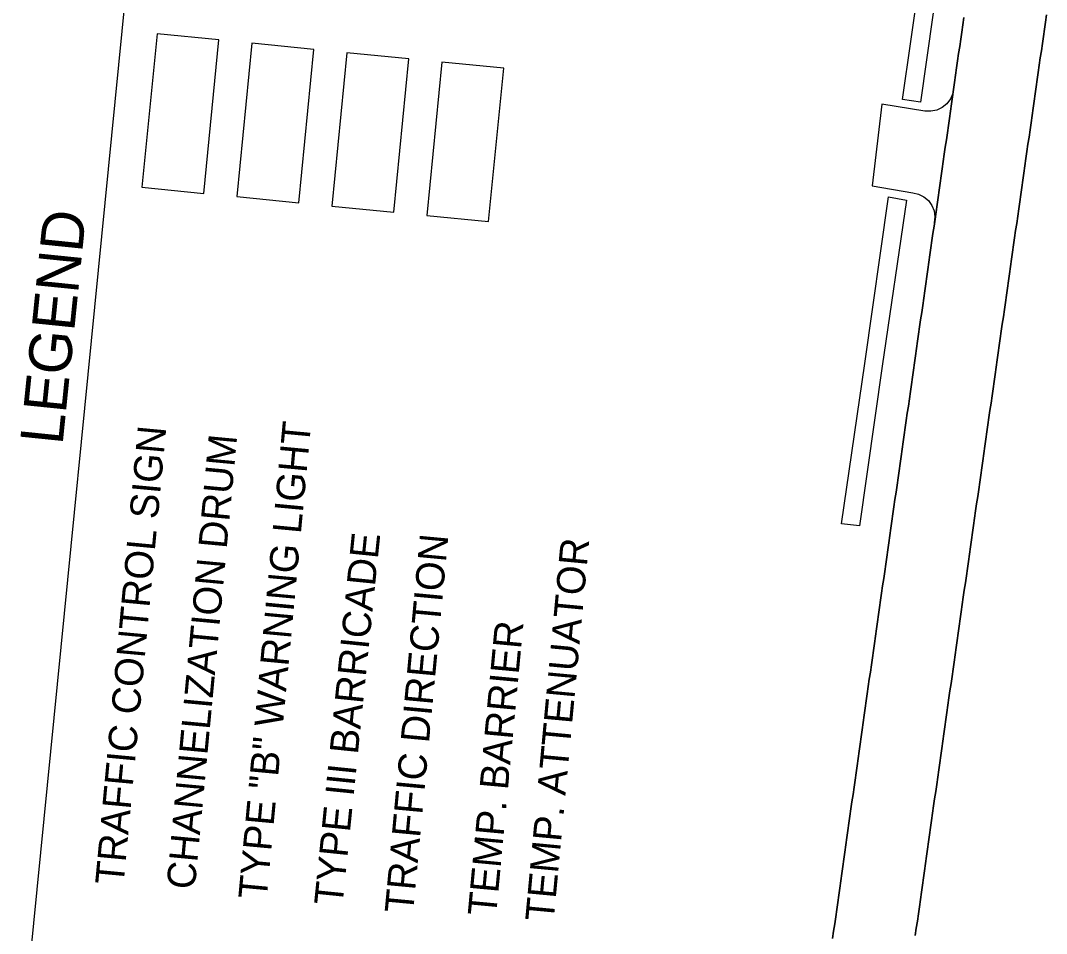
# Model space of a CAD drawing. Extents: x 1795987 to 1799700, y 243690 to 251545.
# Drawn here: x 1797261.2 to 1797542.5, y 247202.7 to 247453.1 of the extents above; entities that cross this region are included whole.
import ezdxf

# ---------------------------------------------------------------- set-up
doc = ezdxf.new("R2010")
doc.units = 0
for name, color, linetype in [('EP', 7, 'Continuous'), ('Level 31', 7, 'Continuous'), ('Prop_Horiz Alignment', 7, 'Continuous')]:
    doc.layers.add(name, color=color, linetype=linetype)

msp = doc.modelspace()

# ---------------------------------------------------------------- linework, layer by layer
at = {"layer": 'EP'}
for p, q in [((1797507.92, 247430.67), (1797502.98, 247431.42)), ((1797499.19, 247404.72), (1797504.07, 247403.85)), ((1797491.2, 247314.5), (1797486.32, 247315.04))]:
    msp.add_line(p, q, dxfattribs=at)
for points in [[(1797502.98, 247431.42), (1797509.89, 247479.28), (1797512.41, 247496.92), (1797513.21, 247499.92), (1797514.39, 247502.79), (1797515.55, 247504.9), (1797517.77, 247509.13), (1797519.86, 247513.31), (1797520.78, 247515.42), (1797521.93, 247518.67), (1797522.28, 247519.96), (1797522.83, 247522.6), (1797523.1, 247524.61), (1797523.26, 247527.63), (1797523.1, 247531.02), (1797522.82, 247533.27), (1797521.91, 247537.81), (1797521.35, 247540.15), (1797520.54, 247543.7), (1797520.12, 247547.31), (1797520.09, 247550.71), (1797523.74, 247576.05), (1797530.2, 247621.54), (1797536.99, 247668.47)], [(1797541.84, 247667.67), (1797535.11, 247620.83), (1797528.62, 247575.39), (1797524.96, 247549.93), (1797525.06, 247548.02), (1797525.55, 247543.91), (1797526.45, 247539.86), (1797526.65, 247538.96), (1797527.41, 247535.59), (1797527.98, 247531.38), (1797528.16, 247527.13), (1797526.97, 247518.48), (1797526.28, 247516.25), (1797524.64, 247511.95), (1797522.63, 247507.8), (1797522.17, 247506.93), (1797521.53, 247505.59), (1797517.43, 247496.48), (1797514.72, 247478.52), (1797507.92, 247430.67)], [(1797486.32, 247315.04), (1797492.66, 247359.05), (1797499.19, 247404.72)], [(1797504.07, 247403.85), (1797497.45, 247358.32), (1797491.2, 247314.5)]]:
    msp.add_lwpolyline(points, dxfattribs=at)
at = {"layer": 'Level 31'}
msp.add_line((1797261.35, 247170.53), (1797308.29, 247644.28), dxfattribs=at)
for points in [[(1797311.42, 247405.67), (1797315.58, 247447.74), (1797298.6, 247449.42), (1797294.43, 247407.35)], [(1797337.45, 247403.09), (1797341.62, 247445.16), (1797324.63, 247446.84), (1797320.46, 247404.77)], [(1797363.49, 247400.51), (1797367.66, 247442.58), (1797350.67, 247444.26), (1797346.5, 247402.19)], [(1797389.53, 247397.93), (1797393.69, 247440), (1797376.71, 247441.68), (1797372.54, 247399.61)]]:
    msp.add_lwpolyline(points, close=True, dxfattribs=at)
at = {"layer": 'Prop_Horiz Alignment'}
for points in [[(1797542.49, 247454.65), (1797542.21, 247452.67), (1797541.93, 247450.7), (1797541.65, 247448.73), (1797541.36, 247446.76), (1797541.08, 247444.78), (1797540.8, 247442.81), (1797540.52, 247440.84), (1797540.24, 247438.87), (1797539.96, 247436.89), (1797539.67, 247434.92), (1797539.39, 247432.95), (1797539.11, 247430.98), (1797538.83, 247429), (1797538.55, 247427.03), (1797538.27, 247425.06), (1797537.99, 247423.09), (1797537.7, 247421.11), (1797537.42, 247419.14), (1797537.14, 247417.17), (1797536.86, 247415.2), (1797536.58, 247413.22), (1797536.3, 247411.25), (1797536.01, 247409.28), (1797535.73, 247407.31), (1797535.45, 247405.33), (1797535.17, 247403.36), (1797534.89, 247401.39), (1797534.61, 247399.42), (1797534.32, 247397.44), (1797534.04, 247395.47), (1797533.76, 247393.5), (1797533.48, 247391.53), (1797533.2, 247389.56), (1797532.92, 247387.58), (1797532.64, 247385.61), (1797532.35, 247383.64), (1797532.07, 247381.67), (1797531.79, 247379.69), (1797531.51, 247377.72), (1797531.23, 247375.75), (1797530.95, 247373.78), (1797530.66, 247371.8), (1797530.38, 247369.83), (1797530.1, 247367.86), (1797529.82, 247365.89), (1797529.54, 247363.91), (1797529.26, 247361.94), (1797528.98, 247359.97), (1797528.69, 247358), (1797528.41, 247356.02), (1797528.13, 247354.05), (1797527.85, 247352.08), (1797527.57, 247350.11), (1797527.29, 247348.13), (1797527, 247346.16), (1797526.72, 247344.19), (1797526.44, 247342.22), (1797526.16, 247340.24), (1797525.88, 247338.27), (1797525.6, 247336.3), (1797525.31, 247334.33), (1797525.03, 247332.35), (1797524.75, 247330.38), (1797524.47, 247328.41), (1797524.19, 247326.44), (1797523.91, 247324.46), (1797523.63, 247322.49), (1797523.34, 247320.52), (1797523.06, 247318.55), (1797522.78, 247316.57), (1797522.5, 247314.6), (1797522.22, 247312.63), (1797521.94, 247310.66), (1797521.65, 247308.68), (1797521.37, 247306.71), (1797521.09, 247304.74), (1797520.81, 247302.77), (1797520.53, 247300.79), (1797520.25, 247298.82), (1797519.96, 247296.85), (1797519.68, 247294.88), (1797519.4, 247292.9), (1797519.12, 247290.93), (1797518.84, 247288.96), (1797518.56, 247286.99), (1797518.28, 247285.01), (1797517.99, 247283.04), (1797517.71, 247281.07), (1797517.43, 247279.1), (1797517.15, 247277.12), (1797516.87, 247275.15), (1797516.59, 247273.18), (1797516.31, 247271.21), (1797516.03, 247269.23), (1797515.75, 247267.26), (1797515.47, 247265.28), (1797515.19, 247263.31), (1797514.91, 247261.34), (1797514.63, 247259.36), (1797514.35, 247257.39), (1797514.07, 247255.41), (1797513.79, 247253.44), (1797513.51, 247251.47), (1797513.23, 247249.49), (1797512.95, 247247.52), (1797512.67, 247245.55), (1797512.39, 247243.57), (1797512.11, 247241.6), (1797511.83, 247239.62), (1797511.55, 247237.65), (1797511.28, 247235.68), (1797511, 247233.7), (1797510.72, 247231.73), (1797510.44, 247229.76), (1797510.16, 247227.78), (1797509.88, 247225.81), (1797509.6, 247223.83), (1797509.32, 247221.86), (1797509.04, 247219.89), (1797508.76, 247217.91), (1797508.48, 247215.94), (1797508.2, 247213.97), (1797507.92, 247211.99), (1797507.64, 247210.02), (1797507.36, 247208.04), (1797507.08, 247206.07), (1797506.8, 247204.1), (1797506.52, 247202.12)], [(1797506.52, 247202.12), (1797506.8, 247204.1), (1797507.08, 247206.07), (1797507.36, 247208.04), (1797507.64, 247210.02), (1797507.92, 247211.99), (1797508.2, 247213.97), (1797508.48, 247215.94), (1797508.76, 247217.91), (1797509.04, 247219.89), (1797509.32, 247221.86), (1797509.6, 247223.83), (1797509.88, 247225.81), (1797510.16, 247227.78), (1797510.44, 247229.76), (1797510.72, 247231.73), (1797511, 247233.7), (1797511.28, 247235.68), (1797511.55, 247237.65), (1797511.83, 247239.62), (1797512.11, 247241.6), (1797512.39, 247243.57), (1797512.67, 247245.55), (1797512.95, 247247.52), (1797513.23, 247249.49), (1797513.51, 247251.47), (1797513.79, 247253.44), (1797514.07, 247255.41), (1797514.35, 247257.39), (1797514.63, 247259.36), (1797514.91, 247261.34), (1797515.19, 247263.31), (1797515.47, 247265.28), (1797515.75, 247267.26), (1797516.03, 247269.23), (1797516.31, 247271.21), (1797516.59, 247273.18), (1797516.87, 247275.15), (1797517.15, 247277.12), (1797517.43, 247279.1), (1797517.71, 247281.07), (1797517.99, 247283.04), (1797518.28, 247285.01), (1797518.56, 247286.99), (1797518.84, 247288.96), (1797519.12, 247290.93), (1797519.4, 247292.9), (1797519.68, 247294.88), (1797519.96, 247296.85), (1797520.25, 247298.82), (1797520.53, 247300.79), (1797520.81, 247302.77), (1797521.09, 247304.74), (1797521.37, 247306.71), (1797521.65, 247308.68), (1797521.94, 247310.66), (1797522.22, 247312.63), (1797522.5, 247314.6), (1797522.78, 247316.57), (1797523.06, 247318.55), (1797523.34, 247320.52), (1797523.63, 247322.49), (1797523.91, 247324.46), (1797524.19, 247326.44), (1797524.47, 247328.41), (1797524.75, 247330.38), (1797525.03, 247332.35), (1797525.31, 247334.33), (1797525.6, 247336.3), (1797525.88, 247338.27), (1797526.16, 247340.24), (1797526.44, 247342.22), (1797526.72, 247344.19), (1797527, 247346.16), (1797527.29, 247348.13), (1797527.57, 247350.11), (1797527.85, 247352.08), (1797528.13, 247354.05), (1797528.41, 247356.02), (1797528.69, 247358), (1797528.98, 247359.97), (1797529.26, 247361.94), (1797529.54, 247363.91), (1797529.82, 247365.89), (1797530.1, 247367.86), (1797530.38, 247369.83), (1797530.66, 247371.8), (1797530.95, 247373.78), (1797531.23, 247375.75), (1797531.51, 247377.72), (1797531.79, 247379.69), (1797532.07, 247381.67), (1797532.35, 247383.64), (1797532.64, 247385.61), (1797532.92, 247387.58), (1797533.2, 247389.56), (1797533.48, 247391.53), (1797533.76, 247393.5), (1797534.04, 247395.47), (1797534.32, 247397.44), (1797534.61, 247399.42), (1797534.89, 247401.39), (1797535.17, 247403.36), (1797535.45, 247405.33), (1797535.73, 247407.31), (1797536.01, 247409.28), (1797536.3, 247411.25), (1797536.58, 247413.22), (1797536.86, 247415.2), (1797537.14, 247417.17), (1797537.42, 247419.14), (1797537.7, 247421.11), (1797537.99, 247423.09), (1797538.27, 247425.06), (1797538.55, 247427.03), (1797538.83, 247429), (1797539.11, 247430.98), (1797539.39, 247432.95), (1797539.67, 247434.92), (1797539.96, 247436.89), (1797540.24, 247438.87), (1797540.52, 247440.84), (1797540.8, 247442.81), (1797541.08, 247444.78), (1797541.36, 247446.76), (1797541.65, 247448.73), (1797541.93, 247450.7), (1797542.21, 247452.67), (1797542.49, 247454.65)], [(1797483.85, 247201.32), (1797484.13, 247203.3), (1797484.41, 247205.27), (1797484.69, 247207.25), (1797484.97, 247209.22), (1797485.25, 247211.19), (1797485.53, 247213.17), (1797485.81, 247215.14), (1797486.09, 247217.11), (1797486.37, 247219.09), (1797486.65, 247221.06), (1797486.93, 247223.03), (1797487.21, 247225.01), (1797487.49, 247226.98), (1797487.77, 247228.96), (1797488.05, 247230.93), (1797488.32, 247232.9), (1797488.6, 247234.88), (1797488.88, 247236.85), (1797489.16, 247238.82), (1797489.44, 247240.8), (1797489.72, 247242.77), (1797490, 247244.74), (1797490.28, 247246.72), (1797490.56, 247248.69), (1797490.84, 247250.67), (1797491.12, 247252.64), (1797491.4, 247254.61), (1797491.68, 247256.59), (1797491.96, 247258.56), (1797492.24, 247260.53), (1797492.52, 247262.51), (1797492.8, 247264.48), (1797493.08, 247266.45), (1797493.36, 247268.43), (1797493.63, 247270.4), (1797493.91, 247272.38), (1797494.19, 247274.35), (1797494.47, 247276.32), (1797494.76, 247278.3), (1797495.04, 247280.27), (1797495.32, 247282.24), (1797495.6, 247284.21), (1797495.88, 247286.19), (1797496.16, 247288.16), (1797496.44, 247290.13), (1797496.73, 247292.1), (1797497.01, 247294.08), (1797497.29, 247296.05), (1797497.57, 247298.02), (1797497.85, 247300), (1797498.13, 247301.97), (1797498.42, 247303.94), (1797498.7, 247305.91), (1797498.98, 247307.89), (1797499.26, 247309.86), (1797499.54, 247311.83), (1797499.82, 247313.8), (1797500.11, 247315.78), (1797500.39, 247317.75), (1797500.67, 247319.72), (1797500.95, 247321.7), (1797501.23, 247323.67), (1797501.51, 247325.64), (1797501.8, 247327.61), (1797502.08, 247329.59), (1797502.36, 247331.56), (1797502.64, 247333.53), (1797502.92, 247335.5), (1797503.2, 247337.48), (1797503.48, 247339.45), (1797503.77, 247341.42), (1797504.05, 247343.39), (1797504.33, 247345.37), (1797504.61, 247347.34), (1797504.89, 247349.31), (1797505.17, 247351.29), (1797505.46, 247353.26), (1797505.74, 247355.23), (1797506.02, 247357.2), (1797506.3, 247359.18), (1797506.58, 247361.15), (1797506.86, 247363.12), (1797507.15, 247365.09), (1797507.43, 247367.07), (1797507.71, 247369.04), (1797507.99, 247371.01), (1797508.27, 247372.99), (1797508.55, 247374.96), (1797508.84, 247376.93), (1797509.12, 247378.9), (1797509.4, 247380.88), (1797509.68, 247382.85), (1797509.96, 247384.82), (1797510.24, 247386.79), (1797510.52, 247388.77), (1797510.81, 247390.74), (1797511.09, 247392.71), (1797511.37, 247394.69), (1797511.65, 247396.66), (1797511.93, 247398.63), (1797512.21, 247400.6), (1797512.5, 247402.58), (1797512.78, 247404.55), (1797513.06, 247406.52), (1797513.34, 247408.49), (1797513.62, 247410.47), (1797513.9, 247412.44), (1797514.19, 247414.41), (1797514.47, 247416.39), (1797514.75, 247418.36), (1797515.03, 247420.33), (1797515.31, 247422.3), (1797515.59, 247424.28), (1797515.88, 247426.25), (1797516.16, 247428.22), (1797516.44, 247430.19), (1797516.72, 247432.17), (1797517, 247434.14), (1797517.28, 247436.11), (1797517.57, 247438.09), (1797517.85, 247440.06), (1797518.13, 247442.03), (1797518.41, 247444), (1797518.69, 247445.98), (1797518.97, 247447.95), (1797519.25, 247449.92), (1797519.54, 247451.89), (1797519.82, 247453.87)], [(1797519.82, 247453.87), (1797519.54, 247451.89), (1797519.25, 247449.92), (1797518.97, 247447.95), (1797518.69, 247445.98), (1797518.41, 247444), (1797518.13, 247442.03), (1797517.85, 247440.06), (1797517.57, 247438.09), (1797517.28, 247436.11), (1797517, 247434.14), (1797516.72, 247432.17), (1797516.44, 247430.19), (1797516.16, 247428.22), (1797515.88, 247426.25), (1797515.59, 247424.28), (1797515.31, 247422.3), (1797515.03, 247420.33), (1797514.75, 247418.36), (1797514.47, 247416.39), (1797514.19, 247414.41), (1797513.9, 247412.44), (1797513.62, 247410.47), (1797513.34, 247408.49), (1797513.06, 247406.52), (1797512.78, 247404.55), (1797512.5, 247402.58), (1797512.21, 247400.6), (1797511.93, 247398.63), (1797511.65, 247396.66), (1797511.37, 247394.69), (1797511.09, 247392.71), (1797510.81, 247390.74), (1797510.52, 247388.77), (1797510.24, 247386.79), (1797509.96, 247384.82), (1797509.68, 247382.85), (1797509.4, 247380.88), (1797509.12, 247378.9), (1797508.84, 247376.93), (1797508.55, 247374.96), (1797508.27, 247372.99), (1797507.99, 247371.01), (1797507.71, 247369.04), (1797507.43, 247367.07), (1797507.15, 247365.09), (1797506.86, 247363.12), (1797506.58, 247361.15), (1797506.3, 247359.18), (1797506.02, 247357.2), (1797505.74, 247355.23), (1797505.46, 247353.26), (1797505.17, 247351.29), (1797504.89, 247349.31), (1797504.61, 247347.34), (1797504.33, 247345.37), (1797504.05, 247343.39), (1797503.77, 247341.42), (1797503.48, 247339.45), (1797503.2, 247337.48), (1797502.92, 247335.5), (1797502.64, 247333.53), (1797502.36, 247331.56), (1797502.08, 247329.59), (1797501.8, 247327.61), (1797501.51, 247325.64), (1797501.23, 247323.67), (1797500.95, 247321.7), (1797500.67, 247319.72), (1797500.39, 247317.75), (1797500.11, 247315.78), (1797499.82, 247313.8), (1797499.54, 247311.83), (1797499.26, 247309.86), (1797498.98, 247307.89), (1797498.7, 247305.91), (1797498.42, 247303.94), (1797498.13, 247301.97), (1797497.85, 247300), (1797497.57, 247298.02), (1797497.29, 247296.05), (1797497.01, 247294.08), (1797496.73, 247292.1), (1797496.44, 247290.13), (1797496.16, 247288.16), (1797495.88, 247286.19), (1797495.6, 247284.21), (1797495.32, 247282.24), (1797495.04, 247280.27), (1797494.76, 247278.3), (1797494.47, 247276.32), (1797494.19, 247274.35), (1797493.91, 247272.38), (1797493.63, 247270.4), (1797493.36, 247268.43), (1797493.08, 247266.45), (1797492.8, 247264.48), (1797492.52, 247262.51), (1797492.24, 247260.53), (1797491.96, 247258.56), (1797491.68, 247256.59), (1797491.4, 247254.61), (1797491.12, 247252.64), (1797490.84, 247250.67), (1797490.56, 247248.69), (1797490.28, 247246.72), (1797490, 247244.74), (1797489.72, 247242.77), (1797489.44, 247240.8), (1797489.16, 247238.82), (1797488.88, 247236.85), (1797488.6, 247234.88), (1797488.32, 247232.9), (1797488.05, 247230.93), (1797487.77, 247228.96), (1797487.49, 247226.98), (1797487.21, 247225.01), (1797486.93, 247223.03), (1797486.65, 247221.06), (1797486.37, 247219.09), (1797486.09, 247217.11), (1797485.81, 247215.14), (1797485.53, 247213.17), (1797485.25, 247211.19), (1797484.97, 247209.22), (1797484.69, 247207.25), (1797484.41, 247205.27), (1797484.13, 247203.3), (1797483.85, 247201.32)], [(1797346.5, 247402.19), (1797363.49, 247400.51), (1797367.66, 247442.58), (1797350.67, 247444.26), (1797346.5, 247402.19)], [(1797516.85, 247433.11), (1797516.85, 247433.11), (1797516.19, 247431.59), (1797515.19, 247430.26), (1797513.9, 247429.22), (1797512.4, 247428.51), (1797510.78, 247428.18), (1797509.12, 247428.24), (1797497.35, 247430.15), (1797494.65, 247407.73), (1797505.83, 247405.84), (1797507.43, 247405.49), (1797508.89, 247404.75), (1797510.13, 247403.69), (1797511.08, 247402.36), (1797511.67, 247400.84), (1797511.88, 247399.22), (1797511.69, 247397.59), (1797511.78, 247397.58), (1797511.93, 247398.63), (1797512.21, 247400.6), (1797512.5, 247402.58), (1797512.78, 247404.55), (1797513.06, 247406.52), (1797513.34, 247408.49), (1797513.62, 247410.47), (1797513.9, 247412.44), (1797514.19, 247414.41), (1797514.47, 247416.39), (1797514.75, 247418.36), (1797515.03, 247420.33), (1797515.31, 247422.3), (1797515.59, 247424.28), (1797515.88, 247426.25), (1797516.16, 247428.22), (1797516.44, 247430.19), (1797516.72, 247432.17), (1797516.85, 247433.11)]]:
    msp.add_lwpolyline(points, dxfattribs=at)

# ---------------------------------------------------------------- texts
at = {"layer": 'Level 31'}
for s, height, rotation, p in [('LEGEND', 11.7, 84.1754, (1797272.68, 247336.47)), ('TYPE "B" WARNING LIGHT', 7.7999, 84.6544, (1797328.64, 247211.85)), ('TRAFFIC CONTROL SIGN', 7.7999, 84.6544, (1797289.39, 247215.75)), ('CHANNELIZATION DRUM', 7.7999, 84.6544, (1797308.94, 247214.55)), ('TYPE III BARRICADE', 7.7999, 84.1754, (1797349.42, 247210.1)), ('TRAFFIC DIRECTION', 7.7999, 84.6544, (1797368.78, 247208.01)), ('TEMP. ATTENUATOR', 7.7999, 84.6544, (1797407.32, 247205.74)), ('TEMP. BARRIER', 7.7999, 84.6544, (1797391.55, 247207.25))]:
    msp.add_text(s, height=height, rotation=rotation, dxfattribs=at).set_placement(p)

doc.saveas('drawing.dxf')
